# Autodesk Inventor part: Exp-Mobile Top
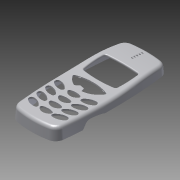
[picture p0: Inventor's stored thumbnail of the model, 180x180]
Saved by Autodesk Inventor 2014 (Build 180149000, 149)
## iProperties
Created: 2008-12
Part Number: Exp-Mobile Top
Document SubType Name: Modeling
Designer: linb
Density: 1 g/cm^3
Material: Generic
Appearance: Default
Translation Standard: STEP AP214IS
FileName: G:\Test Roddin\Mobile Top.stp
PreProcessor: Autodesk Inventor 2010
PostProcessor: Build: 190, Release: 2010 - Date: Wed 12/03/2008
Sent Units: millimeter
Uncertainty: 0.01
Author: linb
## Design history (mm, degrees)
feature "Base1"
body "Solid1"
